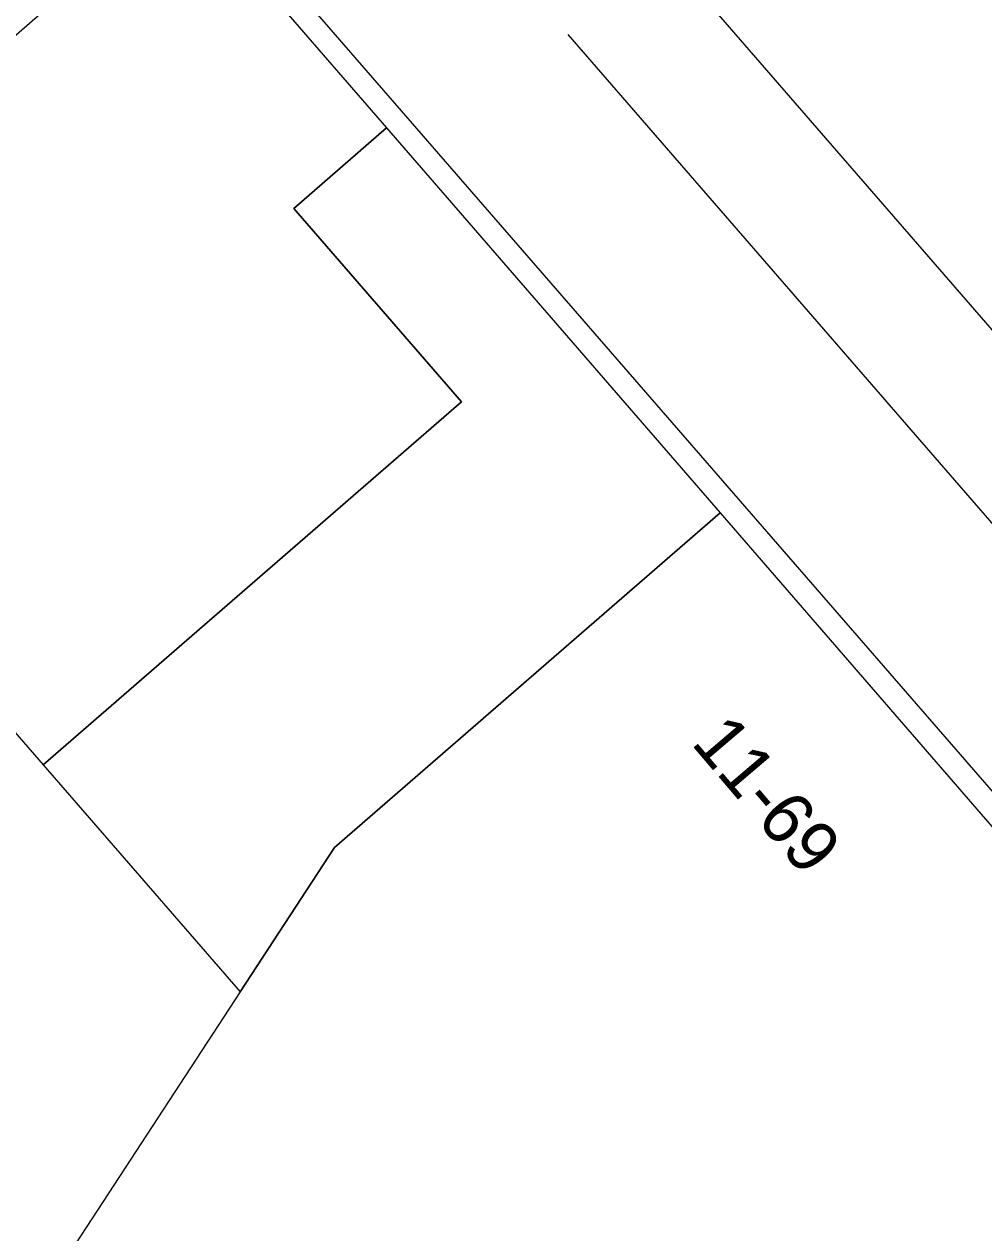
# Model space of a CAD drawing. Extents: x 155640 to 156810, y 382822 to 384046.
# Drawn here: x 156490.98 to 156509.49, y 383754.11 to 383777.43 of the extents above; entities that cross this region are included whole.
import ezdxf

# ---------------------------------------------------------------- set-up
doc = ezdxf.new("R2010")
doc.units = 0
for name, color, linetype in [('IMGEO_Lijnafwatering', 7, 'Continuous'), ('IMGEO_Muur', 7, 'Continuous'), ('IMGEO_Pand', 7, 'Continuous'), ('IMGEO_Pand_nummerreeks', 7, 'Continuous'), ('IMGEO_Pand_overbouw', 7, 'Continuous'), ('IMGEO_Voetgangersgebied_open', 7, 'Continuous'), ('IMGEO_Voetpad_open', 7, 'Continuous')]:
    doc.layers.add(name, color=color, linetype=linetype)

msp = doc.modelspace()

# ---------------------------------------------------------------- linework, layer by layer
at = {"layer": 'IMGEO_Lijnafwatering'}
msp.add_lwpolyline([(156513.947, 383762.849), (156501.468, 383777.231)], dxfattribs=at)
at = {"layer": 'IMGEO_Muur'}
msp.add_lwpolyline([(156497.967, 383775.43), (156504.403, 383768.001)], dxfattribs=at)
at = {"layer": 'IMGEO_Pand'}
for points in [[(156484.208, 383771.362), (156484.378, 383771.622), (156494.004, 383780.006), (156497.967, 383775.43)], [(156491.34, 383763.141), (156499.415, 383770.147), (156496.178, 383773.878), (156497.967, 383775.43)], [(156484.606, 383770.903), (156491.34, 383763.141)], [(156504.403, 383768.001), (156526.125, 383742.921), (156525.429, 383738.064), (156524.746, 383738.162), (156523.866, 383731.807), (156524.529, 383731.715), (156519.308, 383694.178), (156518.219, 383694.329), (156517.212, 383687.287), (156518.313, 383687.13), (156516.68, 383675.304), (156436.208, 383686.52), (156438.014, 383699.718), (156438.115, 383699.703), (156438.461, 383700.239)], [(156504.403, 383768.001), (156496.961, 383761.545), (156495.141, 383758.761)], [(156495.141, 383758.761), (156489.522, 383750.169), (156483.796, 383750.953), (156467.607, 383726.148), (156463.541, 383696.89), (156450.981, 383698.723), (156451.111, 383699.61), (156451.369, 383699.433), (156453.11, 383701.958), (156448.797, 383704.86), (156447.156, 383702.372), (156442.019, 383705.761)]]:
    msp.add_lwpolyline(points, dxfattribs=at)
at = {"layer": 'IMGEO_Pand_overbouw'}
msp.add_lwpolyline([(156522.244, 383748.131), (156489.331, 383786.036), (156489.254, 383786.124), (156477.703, 383776.08), (156477.589, 383775.981), (156481.391, 383771.435), (156483.001, 383769.51), (156484.606, 383770.903), (156484.208, 383771.362), (156484.378, 383771.622), (156494.004, 383780.006), (156497.967, 383775.43), (156496.178, 383773.878), (156499.415, 383770.147), (156491.34, 383763.141), (156495.141, 383758.761), (156496.961, 383761.545), (156504.403, 383768.001), (156526.125, 383742.921)], dxfattribs=at)
at = {"layer": 'IMGEO_Voetgangersgebied_open'}
msp.add_lwpolyline([(156515.843, 383775.339), (156510.412, 383770.654), (156502.001, 383780.354), (156509.534, 383784.434), (156515.843, 383775.339)], dxfattribs=at)
at = {"layer": 'IMGEO_Voetpad_open'}
for points in [[(156517.613, 383674.051), (156518.79, 383682.442), (156518.138, 383682.533), (156525.621, 383736.263), (156526.284, 383736.173), (156527.289, 383743.325), (156522.761, 383748.566), (156522.244, 383748.131), (156489.331, 383786.036), (156489.254, 383786.124), (156477.703, 383776.08), (156477.589, 383775.981)], [(156497.967, 383775.43), (156504.403, 383768.001)], [(156491.34, 383763.141), (156495.141, 383758.761)]]:
    msp.add_lwpolyline(points, dxfattribs=at)

# ---------------------------------------------------------------- texts
at = {"layer": 'IMGEO_Pand_nummerreeks'}
msp.add_text('11-69', height=1, rotation=310.4171, dxfattribs=at).set_placement((156503.824, 383763.554))

doc.saveas('drawing.dxf')
